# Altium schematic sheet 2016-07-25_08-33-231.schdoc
size 223 x 111 mm; SheetNumber: 1; SheetTotal: 1
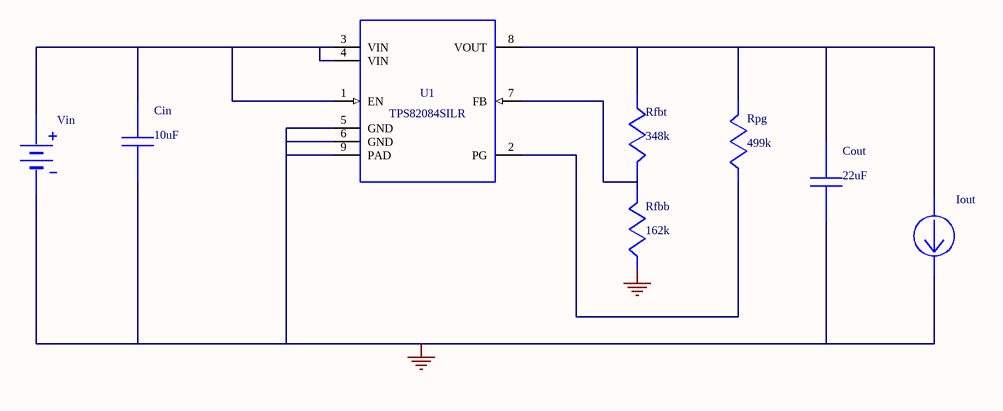
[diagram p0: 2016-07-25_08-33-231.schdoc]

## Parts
Cin  value 10uF  (hidden comment: LMK212BJ106KG-T)
Cout  value 22uF  (hidden comment: JMK212BJ226KG-T)
Iout  WB_CURRENT_LOAD  (value not drawn)
Rfbb  value 162k  (hidden comment: CRCW0402162KFKED)
Rfbt  value 348k  (hidden comment: CRCW0402348KFKED)
Rpg  value 499k  (hidden comment: CRCW0402499KFKED)
U1  TPS82084SILR
Vin  WB_BATTERY  (value not drawn)

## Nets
0: Cin.2 Cout.2 Iout.2(-) Rfbb.2 U1.5(GND) U1.6(GND) U1.9(PAD) Vin.2(-)
NetCin_1: Cin.1 U1.1(EN) U1.3(VIN) U1.4(VIN) Vin.1(+)
NetCout_1: Cout.1 Iout.1(+) Rfbt.2 Rpg.1 U1.8(VOUT)
NetRfbb_1: Rfbb.1 Rfbt.1 U1.7(FB)
NetRpg_2: Rpg.2 U1.2(PG)

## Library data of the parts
Cin = LMK212BJ106KG-T: Manufacturer Name: Taiyo Yuden
Cout = JMK212BJ226KG-T: Manufacturer Name: Taiyo Yuden
Rfbb = CRCW0402162KFKED: Manufacturer Name: Vishay-Dale
Rfbt = CRCW0402348KFKED: Manufacturer Name: Vishay-Dale
Rpg = CRCW0402499KFKED: Manufacturer Name: Vishay-Dale
U1 = TPS82084SILR: Manufacturer Name: Texas Instruments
